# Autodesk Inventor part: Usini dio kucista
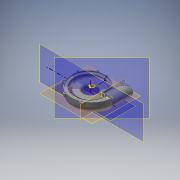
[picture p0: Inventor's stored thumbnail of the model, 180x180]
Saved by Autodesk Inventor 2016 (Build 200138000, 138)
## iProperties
Created: 2015-03
Part Number: Usini dio kucista
Material: Generic
Document SubType Name: Modeling
Designer: Uglješa
Density: 1 g/cm^3
Appearance: Default
Mass: 847.681 g
Surface Area: 2346.56 cm^2
Volume: 847.681 cm^3
Author: Uglješa
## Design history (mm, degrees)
sketch "Sketch1"
  geometry: L1 (0, 36.378)-(0, -65.866) reference; L2 (105, -10)-(105, 10); L3 (105, 10)-(102, 10); L4 (102, 10)-(102, 2); L5 (102, 2)-(90, 2); L6 (90, 2)-(90, -2); L7 (51.654, -17)-(51.654, -12); L8 (51.654, -17)-(80, -17); L9 (83.626, -12)-(51.654, -12); A1 r 13.48 centre (91.52, -10) between (80, -17) and (105, -10); A2 r 8.143 centre (91.52, -10) between (83.626, -12) and (90, -2); 1 further point
  constraints: 18 end point, 4 point on circle, 3 perpendicular, 2 centre point, 1 coincident, 1 horizontal, 1 parallel, 1 tangent, 1 vertical
  dimensions: "d25" = 8 distance between parallel lines of L3 L5; "d28" = 10 vertical distance of point (0, 0) A1.centre; "d151" = 12 distance from line of point (0, 0) L9; "d152" = 5 distance between parallel lines of L8 L9; "d344" = 15 distance between parallel lines of L6 L2; "d365" = 210 diameter of L2 L1; "d509" = 2 distance from line of point (0, 0) L5; "d514" = 4 distance of L5.end L6.end; "d616" = 25 distance from line of L2 L8.end; "d670" = 3 distance of L2.end L3.end
sketch "Sketch2"
  geometry: L1 (53.134, -17)-(80, -17); L2 (0, 0)-(0, -94.804) reference; L3 (53.134, -12)-(86.237, -12); L4 (120, -16)-(120, -0.062); L5 (103, -2)-(103, 2); L6 (117, 10)-(120, 10); L7 (120, 10)-(120, -0.062); L8 (53.134, -12)-(53.134, -17); L9 (117, 10)-(117, 2); L10 (117, 2)-(103, 2); A1 r 14.32 centre (99.987, -16) between (86.237, -12) and (103, -2); A2 r 20.013 centre (99.987, -16) between (80, -17) and (120, -16)
  constraints: 20 end point, 4 point on circle, 3 perpendicular, 2 centre point, 1 coincident, 1 collinear, 1 parallel, 1 tangent, 1 vertical
  dimensions: "d39" = 12 distance from line of L3 L2.start; "d42" = 5 distance between parallel lines of L3 L1; "d50" = 16 vertical distance of L2.start A1.centre; "d184" = 17 distance between parallel lines of L7 L5; "d350" = 2 distance from line of L2.start L10; "d351" = 8 distance between parallel lines of L6 L10; "d364" = 240 diameter of L4 L2; "d513" = 4 distance of L5.start L5.end; "d617" = 40 distance from line of L4 L1.end; "d671" = 3 distance of L6.start L6.end
sketch "Sketch3"
  geometry: L1 (0, -126.8)-(0, 28.645) reference; L2 (-61.778, -17)-(-75, -17); L3 (-61.778, -12)-(-84.03, -12); L4 (-130, -22)-(-130, 10); L5 (-108, -2)-(-108, 2); L6 (-108, 2)-(-127, 2); L7 (-127, 2)-(-127, 10); L8 (-127, 10)-(-130, 10); L9 (-61.778, -12)-(-61.778, -17); A1 r 27.727 centre (-102.273, -22) between (-130, -22) and (-75, -17); A2 r 20.804 centre (-102.273, -22) between (-108, -2) and (-84.03, -12); 1 further point
  constraints: 18 end point, 4 point on circle, 3 perpendicular, 3 vertical, 2 centre point, 2 parallel, 1 coincident, 1 tangent
  dimensions: "d62" = 5 distance between parallel lines of L2 L3; "d64" = 12 distance from line of point (0, 0) L3; "d70" = 8 distance of L6.end L7.end; "d72" = 2 distance from line of L6 point (0, 0); "d74" = 22 vertical distance of point (0, 0) A1.centre; "d186" = 22 distance between parallel lines of L4 L5; "d368" = 260 diameter of L4 L1; "d515" = 4 distance of L5.start L5.end; "d618" = 55 distance from line of L4 L2.end; "d678" = 3 distance of L7.end L4.end
sketch "Sketch4"
  geometry: L1 (0, 0)-(0, 390.533); L2 (0, 0)-(-377.579, 0); L3 (-120, 0)-(-120, -351.799); L4 (0, 105)-(221.176, 105); A1 r 105.938 centre (-14.063, 0) between (0, 105) and (-120, 0)
  constraints: 8 end point, 2 point on circle, 2 point on line, 2 vertical, 1 centre point, 1 horizontal, 1 perpendicular, 1 tangent
  dimensions: "d359" = 105 distance of L4.start L1.start; "d363" = 120 distance of L3.start L1.start
sketch "Sketch7"
  geometry: L1 (0, 0)-(0, -210.072); L2 (-140, -30)-(-140, 10); L3 (-140, 10)-(-137, 10); L4 (-137, 10)-(-137, 2); L5 (-137, 2)-(-106.2, 2); L6 (-106.2, 2)-(-106.2, -2); L7 (-84.752, -12)-(-48.748, -12); L8 (-48.748, -12)-(-48.748, -17); L9 (-48.748, -17)-(-75, -17); A1 r 33.8 centre (-106.2, -30) between (-140, -30) and (-75, -17); A2 r 28 centre (-106.2, -30) between (-106.2, -2) and (-84.752, -12)
  constraints: 18 end point, 4 parallel, 4 point on circle, 3 perpendicular, 2 centre point, 2 vertical, 1 coincident, 1 point on line, 1 tangent
  dimensions: "d102" = 8 distance of L3.end L4.end; "d103" = 28 radius of A2; "d207" = 2 vertical distance of L1.start L6.end; "d209" = 5 distance of L7.end L8.end; "d210" = 12 distance from line of L1.start L7; "d375" = 280 diameter of L2 L1; "d516" = 22 distance between parallel lines of L3 L7; "d619" = 65 distance from line of L9.end L2; "d679" = 3 distance of L2.end L3.end
loft "Loft4" dims "d672" = 10, "d673" = 90 deg, "d674" = 10, "d675" = 90 deg, "d676" = 0, "d677" = 90 deg
sketch "Sketch11"
  geometry: L1 (40, -27)-(40, -39.604); L2 (50, -42)-(55, -42); L3 (55, -42)-(55, -22); L4 (60, -17)-(77.651, -17); L5 (55, -12)-(77.651, -12); L6 (0, 0)-(0, -85.323); L7 (77.651, -17)-(77.651, -12); L8 (50, -60)-(48, -60); L9 (50, -60)-(50, -42); A1 r 30 centre (70, -39.604) between (40, -39.604) and (48, -60); A2 r 15 centre (55, -27) between (55, -12) and (40, -27); A3 r 5 centre (60, -22) between (60, -17) and (55, -22); 1 further point
  constraints: 18 end point, 6 point on circle, 5 tangent, 3 centre point, 2 parallel, 2 perpendicular, 2 point on line, 2 vertical, 1 horizontal
  dimensions: "d136" = 5 distance between parallel lines of L5 L4; "d138" = 15 radius of A2; "d139" = 80 diameter of L1 L6; "d141" = 30 radius of A1; "d144" = 17 distance from line of L6.start L4; "d193" = 5 radius of A3; "d414" = 18 distance between parallel lines of L2 L8; "d416" = 100 diameter of L9 L6; "d417" = 42 distance from line of L6.start L2; "d418" = 2 distance of L8.start L8.end; "d662" = 5 distance between parallel lines of L9 L3
sketch "Sketch12"
  geometry: L1 (-120, 0)-(-120, 196.1); L2 (0, 0)-(0, 238.053); A1 r 130.417 centre (10.417, 0) between (-120, 0) and (0, -130)
  constraints: 4 end point, 2 point on circle, 2 vertical, 1 centre point, 1 point on line, 1 tangent
  dimensions: "d369" = 130 distance of A1.end L2.start; "d370" = 120 distance of L2.start L1.start; "d371" = 120 distance from line of L2.start L1
loft "Loft5" sketch "Sketch12" dims "d187" = 0, "d188" = 90 deg, "d189" = 0, "d190" = 90 deg, "d372" = 0, "d373" = 90 deg
sketch "Sketch13"
  geometry: L1 (0, 0)-(185.048, 0); L2 (0, 0)-(0, -182.275); L3 (0, 0)-(487.793, 0); L4 (0, 0)-(0, -482.564); L5 (140, 0)-(140, 388.334); A1 r 130.357 centre (9.643, 0) between (0, -130) and (140, 0); 2 further points
  constraints: 10 end point, 4 point on line, 2 horizontal, 2 point on circle, 2 vertical, 1 centre point, 1 perpendicular, 1 tangent
  dimensions: "d376" = 140 distance of L1.start L5.start; "d377" = 130 distance of L1.start A1.start
workplane "Work Plane3"
workplane "Work Plane6"
sketch "Sketch34"
  geometry: L1 (113.093, 65.922)-(96.417, 49.246); L2 (47.171, 85.264)-(47.171, 65.141); L3 (92.893, -45.721)-(111.926, -64.755); L4 (47.171, -67.337)-(47.171, -94.636); L5 (-0.858, -48.029)-(-16.786, -63.958); L6 (47.171, 0)-(331.223, 0); L7 (-2.517, 49.689)-(1.756, 45.416); L8 (-27.461, 0)-(-54.951, 0); L9 (47.171, 0)-(-109.659, 0); L10 (144.214, 0)-(113.093, 0)
  constraints: 20 end point, 9 point on line, 2 horizontal, 2 perpendicular, 1 vertical
  dimensions: "d262" = 45 deg angle of L1 L6; "d263" = 45 deg angle of L1 L2; "d264" = 45 deg angle of L5 L4; "d265" = 45 deg angle of L2 L7
loft "Loft8" dims "d378" = 0, "d379" = 90 deg, "d380" = 0, "d381" = 90 deg, "d382" = 0, "d383" = 90 deg
  node "Edges3"
revolve "Revolution3" stored, may be unused: angle "d419" = 90 deg
sketch "Sketch55"
  geometry: L1 (55, -22)-(55, -42) reference; L2 (55, -30)-(102.194, -23.367); L3 (55, -30)-(55, -22); L4 (55, -22)-(100, -22); A1 r 15 centre (109, -10) between (100, -22) and (119.658, -20.555) reference; A2 r 15 centre (109, -10) between (100, -22) and (102.194, -23.367); 1 further point
  constraints: 6 end point, 3 point on circle, 1 centre point, 1 concentric, 1 horizontal, 1 point on line, 1 vertical
  dimensions: "d460" = 8 distance from line of L4 L2.start; "d461" = 8 deg angle of L4 L2
workplane "Work Plane14"
fillet "Fillet22" dims "d480" = 2
chamfer "Chamfer2" distance "d481" = 2; stored, may be unused: second distance "d482" = 2, angle "d483" = 45 deg
workplane "Work Plane15"
sketch "Sketch59"
  geometry: L1 (0, 0)-(0, 270.285); L2 (0, 0)-(203.327, 0); L3 (140, 0)-(139.966, 78); L4 (139.966, 78)-(141.966, 80); L5 (736.882, 1.819)-(736.828, 125); L6 (106.2, 0)-(106.2, 152.997); L7 (137.474, 120)-(144.101, 120); L8 (139.759, 105)-(145.151, 105); L9 (78.2, 0)-(134.2, 0) reference; L10 (134.2, 0)-(134.2, 130); L11 (134.2, 130)-(141.944, 130); L12 (141.966, 80)-(141.956, 102.042); L13 (141.954, 107.958)-(141.95, 117.042); L14 (141.947, 122.958)-(141.944, 130); L15 (134.2, 0)-(140, 0); A1 r 3 centre (142.448, 120) between (141.947, 122.958) and (141.95, 117.042); A2 r 3 centre (142.455, 105) between (141.954, 107.958) and (141.956, 102.042); 3 further points; 1 other entity
  constraints: 28 end point, 5 parallel, 4 point on circle, 3 collinear, 3 vertical, 2 centre point, 2 point on line, 1 horizontal, 1 midpoint, 1 perpendicular, 2 other
  dimensions: "d492" = 2 horizontal distance of L3.end L4.end; "d493" = 2 horizontal distance of L3.end L4.end; "d495" = 250 diameter of L5.end L2; "d623" = 3 radius of A2; "d624" = 3 radius of A1; "d629" = 130 distance from line of L11 L3.start; "d631" = 0 deg angle of L11 L7; "d632" = 10 distance from line of L11 L7.end; "d633" = 25 distance from line of L11 L8.end; "d634" = 50 distance from line of L11 L4.end; "d635" = 0.5 distance from line of L13 A2.centre; "d636" = 0.5 distance from line of L14 A1.centre
revolve "Revolution4" sketch "Sketch59" stored, may be unused: angle "d498" = 90 deg
sketch "Sketch62"
  geometry: L1 (-153, 8)-(-63.5, 8) reference; L2 (-51.5, 8)-(-63.5, 8) reference; L3 (-153, 8)-(-51.5, 8) reference; L4 (-153, 8)-(-288, 8) reference; L5 (-288, 8)-(-153, 8) reference; L6 (-153, 8)-(0, 8) reference; L7 (-12.122, 8)-(0, 8) reference; L8 (-12.122, 8)-(-13.881, 8) reference; L9 (-13.881, 8)-(-20.97, 8) reference; L10 (-153, 8)-(-20.97, 8) reference; L11 (-153, 8)-(-276, 8) reference; L12 (-153, 8)-(-276, 8) reference; L13 (-30.8, 8)-(0, 8) reference; L14 (-2.155, 8)-(-44.654, 8); L15 (-44.654, 8)-(-44.654, -28.051); L16 (-44.654, -28.051)-(-2.155, -28.051); L17 (-2.155, -28.051)-(-2.155, 8); 2 further points
  constraints: 8 end point, 2 parallel, 1 horizontal, 1 perpendicular, 1 point on line
extrude "Extrusion7" cut sketch "Sketch62" distance "d517" = 20; taper "d518" = 0 deg
workplane "Work Plane20"
workplane "Work Plane23"
sketch "Sketch63"
  geometry: L1 (-7.774, 7.255)-(180.406, 7.255); L2 (-7.774, 7.255)-(-264.35, 7.255); L3 (-53.15, -123.454)-(-51.856, -118.625); L4 (-51.856, -118.625)-(-32.537, -123.801); L5 (-33.831, -128.631)-(-32.537, -123.801); L6 (-125.357, -49.084)-(-121.027, -46.584); L7 (-121.027, -46.584)-(-111.027, -63.905); L8 (-115.357, -66.405)-(-111.027, -63.905); L9 (-125.926, 49.267)-(-121.096, 47.973); L10 (-121.096, 47.973)-(-126.273, 28.654); L11 (-131.102, 29.948)-(-126.273, 28.654); L12 (-60.113, 117.91)-(-57.613, 113.58); L13 (-57.613, 113.58)-(-74.934, 103.58); L14 (-77.434, 107.91)-(-74.934, 103.58); L15 (31.391, 114.783)-(30.097, 109.953); L16 (30.097, 109.953)-(10.778, 115.129); L17 (12.073, 119.959)-(10.778, 115.129); L18 (-7.774, 7.255)-(36.411, 172.155); L19 (-7.774, 7.255)-(-95.441, 159.1); L20 (-7.774, 7.255)-(-180.234, 53.466); L21 (-7.774, 7.255)-(-169.432, -86.078); L22 (-7.774, 7.255)-(-59.857, -187.122); L23 (-7.774, 7.255)-(86.188, -155.491); A1 r 10 centre (-43.491, -126.042) between (-53.15, -123.454) and (-33.831, -128.631); A2 r 10 centre (-120.357, -57.745) between (-125.357, -49.084) and (-115.357, -66.405); A3 r 10 centre (-128.514, 39.608) between (-125.926, 49.267) and (-131.102, 29.948); A4 r 10 centre (-68.774, 112.91) between (-60.113, 117.91) and (-77.434, 107.91); A5 r 10 centre (21.732, 117.371) between (31.391, 114.783) and (12.073, 119.959)
  constraints: 46 end point, 14 perpendicular, 10 point on circle, 10 tangent, 5 centre point, 5 point on line, 2 horizontal
  dimensions: "d544" = 45 deg angle of L19 L18; "d545" = 45 deg angle of L20 L19; "d546" = 45 deg angle of L21 L20; "d547" = 45 deg angle of L22 L21; "d548" = 5 distance from line of A1.centre L4; "d549" = 0 deg angle of L3 L5; "d550" = 10 radius of A1; "d552" = 5 distance from line of A2.centre L7; "d555" = 10 radius of A3; "d556" = 5 distance from line of L10 A3.centre; "d558" = 10 radius of A4; "d559" = 5 distance from line of L13 A4.centre; "d561" = 10 radius of A5; "d563" = 5 distance from line of A5.centre L16; "d568" = 114 distance of L1.start A5.centre; "d569" = 122 distance of L1.start A4.centre; "d571" = 130 distance of A2.centre L1.start; "d572" = 138 distance of L1.start A1.centre; "d599" = 45 deg angle of L22 L23; "d611" = 120 distance from line of L1.start L10; "d731" = 10 radius of A2
extrude "Extrusion8" join sketch "Sketch63" distance "d526" = 20; taper "d527" = 0 deg
workplane "Work Plane22"
workplane "Work Plane21"
workplane "Work Plane24"
fillet "Fillet30" dims "d627" = 1
workplane "Work Plane19"
sketch "Sketch73"
  geometry: L1 (0, 36.378)-(0, -65.866) reference; L2 (-5, 20)-(-5, 40); L3 (-5, 40)-(-8, 40); L4 (-8, 40)-(-8, 32); L5 (-8, 32)-(-20, 32); L6 (-20, 32)-(-20, 28); L7 (-56.345, 13)-(-56.345, 18); L8 (-56.345, 13)-(-30, 13); L9 (-26.374, 18)-(-56.345, 18); L10 (54.915, 40)-(-65, 40) reference; A1 r 13.48 centre (-18.48, 20) between (-30, 13) and (-5, 20); A2 r 8.143 centre (-18.48, 20) between (-26.374, 18) and (-20, 28); 3 further points
  constraints: 20 end point, 4 point on circle, 3 perpendicular, 2 centre point, 2 horizontal, 1 coincident, 1 collinear, 1 parallel, 1 point on line, 1 tangent, 1 vertical, 3 other
  dimensions: "d638" = 8 distance between parallel lines of L3 L5; "d639" = 10 vertical distance of point (0, 30) A1.centre; "d640" = 12 distance from line of point (0, 30) L9; "d641" = 5 distance between parallel lines of L8 L9; "d642" = 15 distance between parallel lines of L6 L2; "d644" = 2 distance from line of point (0, 30) L5; "d645" = 12 distance between parallel lines of L6 L4; "d646" = 4 distance of L5.end L6.end; "d647" = 25 distance from line of L2 L8.end; "d650" = 5 distance from line of point (0, 30) L2
sketch "Sketch52"
  geometry: L1 (0, 0)-(265.787, 0); L2 (0, 0)-(0, 443.042); L3 (78.2, 557.858)-(78.2, -245.858) reference; L4 (78.2, 130)-(78.2, 0) reference; L5 (0, 83.626)-(0, 99.663) reference; A1 r 119.037 centre (-15.843, -12.978) between (78.2, 60) and (0, 105); 3 further points; 1 other entity
  constraints: 4 end point, 2 point on circle, 2 point on line, 1 centre point, 1 horizontal, 1 vertical, 2 other
  dimensions: "d390" = 105 distance of L1.start A1.end; "d637" = 60 vertical distance of L1.start A1.start
loft "Loft11" sketch "Sketch73", "Sketch52" dims "d651" = 0, "d652" = 90 deg, "d653" = 0, "d654" = 90 deg, "d655" = 0, "d656" = 90 deg
  node "Edges6"
sketch "Sketch65"
  geometry: A1 r 10 centre (23.604, 116.802) between (33.252, 114.174) and (13.955, 119.431) reference; A2 r 10 centre (-66.919, 112.72) between (-58.238, 117.683) and (-75.6, 107.756) reference; A3 r 10 centre (-126.966, 39.667) between (-124.337, 49.315) and (-129.594, 30.019) reference; A4 r 10 centre (-119.215, -57.719) between (-124.179, -49.037) and (-114.251, -66.4) reference; A5 r 10 centre (-42.634, -126.337) between (-52.283, -123.708) and (-32.986, -128.965) reference
hole "Hole2" sketch "Sketch65" at (23.604, 116.802), (-66.919, 112.72), (-126.966, 39.667), (-119.215, -57.719), (-42.634, -126.337) diameter "d580" = 9; stored, may be unused: countersink angle "d584" = 90 deg, drill point angle "d586" = 118 deg; dims "d581" = 6, "d582" = 24, "d583" = 6.3, "d585" = 10
sketch "Sketch74"
  geometry: L1 (54, 40)-(-65, 40) reference; L2 (-5, 40)-(-65, 40); L3 (-65, 40)-(-65, 7); L4 (-65, 7)-(-10, 7); L5 (-5, 12)-(-5, 40); L6 (-5, 12)-(-10, 12); L7 (-10, 12)-(-10, 7); L8 (-65, 18)-(-65, 33.8) reference; 5 further points; 2 other entities
  constraints: 14 end point, 3 horizontal, 2 parallel, 2 perpendicular, 1 point on line, 4 other
  dimensions: "d659" = 33 distance between parallel lines of L1 L4; "d660" = 5 distance of L6.end L4.end; "d661" = 5 distance of L5.start L6.end
extrude "Extrusion11" join sketch "Sketch74" distance "d657" = 2; taper "d658" = 0 deg
sketch "Sketch75"
  geometry: L1 (-30, -14)-(-21.448, -14) reference; L2 (0, -4)-(0, 0) reference; L3 (0, 0)-(10.883, 0) reference; L4 (-28, 8)-(-28, -13.067) reference; L5 (-28, 8)-(-30, 8) reference; L6 (-30, -14)-(-30, 8) reference; L7 (-30, 8)-(33, 8); L8 (33, 8)-(33, 0); L9 (33, 0)-(0, 0); A1 r 28 centre (0, -32) between (0, -4) and (-21.448, -14) reference; A2 r 33.8 centre (0, -32) between (10.883, 0) and (-28, -13.067) reference; 1 further point
  constraints: 6 end point, 2 perpendicular, 1 point on line
  dimensions: "d667" = 63 distance of L5.end L7.end
extrude "Extrusion12" join sketch "Sketch75" distance "d664" = 2; taper "d665" = 0 deg
workplane "Work Plane25"
fillet "Fillet34" dims "d708" = 10
fillet "Fillet35" dims "d709" = 10
fillet "Fillet36" dims "d710" = 10
fillet "Fillet38" dims "d712" = 5
fillet "Fillet39" dims "d713" = 5
fillet "Fillet41" dims "d715" = 6
fillet "Fillet43" dims "d717" = 5
fillet "Fillet46" dims "d727" = 5
fillet "Fillet48" dims "d729" = 2
fillet "Fillet49" dims "d730" = 2
workplane "Work Plane26"
sketch "Sketch79"
  geometry: L1 (-178.2, 2.541)-(-178.2, 74.293); L2 (-178.2, 74.293)-(-166.2, 74.293); L3 (-166.2, 74.293)-(-166.2, 2.541); L4 (-166.2, 2.541)-(-178.2, 2.541); L5 (-138.2, 130)-(-194.2, 130) reference; L6 (-200.259, 78.293)-(-132.141, 78.293) reference; L7 (-166.2, 130)-(-166.2, -187.613); 3 further points
  constraints: 2 end point, 1 collinear, 1 midpoint, 1 point on line, 1 vertical, 2 other
  dimensions: "d733" = 12 distance of L2.end L1.end; "d740" = 4 distance between parallel lines of L6 L2
emboss "Emboss6" sketch "Sketch79" dims "d62" = 5, "d737" = 1, "d738" = 0
body "Solid2"
node "Projected Loop3"
other parameters: "d26" = 12, "d37" = 15, "d625" = 0.5, "d626" = 0.5, "d680" = 5, "d732" = 46.8
